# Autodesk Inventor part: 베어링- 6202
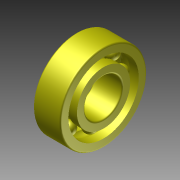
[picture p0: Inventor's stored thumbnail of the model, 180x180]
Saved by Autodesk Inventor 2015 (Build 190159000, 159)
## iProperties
Created: 2025-08
Part Number: 베어링- 6202
Material: 일반
Document SubType Name: Modeling
Designer: USER
Density: 1 g/cm^3
Appearance: 기본값
Author: USER
Author: jhkim
Description: 깊은 그루브 볼 베어링
Creation Date: 2025-08-05
Sending System: Autodesk Inventor 2026
Preprocessor: ST-DEVELOPER v20.1
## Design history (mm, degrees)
node "베어링- 62021"
body "Solid1"
node "Solid1_1"
node "Solid1_2"
node "Solid1_3"
node "Solid1_4"
node "Solid1_5"
node "Solid1_6"
node "Solid1_7"
node "Solid1_8"
node "Solid1_9"
node "기준1"
node "기준2"
node "기준3"
node "기준4"
node "기준5"
node "기준6"
node "기준7"
node "기준8"
node "기준9"
node "기준10"
